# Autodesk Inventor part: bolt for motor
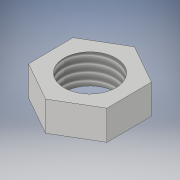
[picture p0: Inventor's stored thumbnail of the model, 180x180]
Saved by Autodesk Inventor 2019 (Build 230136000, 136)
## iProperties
Created: 2019-10
Part Number: bolt for motor
Material: Generic
Document SubType Name: Modeling
Designer: Asus
Density: 1 g/cm^3
Appearance: Default
Author: Asus
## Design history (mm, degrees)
sketch "Sketch1"
  geometry: 1 further point
sketch "Sketch2"
  geometry: L1 (10.441, 6.163)-(10.558, -5.961); L2 (10.558, -5.961)-(0.117, -12.124); L3 (0.117, -12.124)-(-10.441, -6.163); L4 (-10.441, -6.163)-(-10.558, 5.961); L5 (-10.558, 5.961)-(-0.117, 12.124); L6 (-0.117, 12.124)-(10.441, 6.163); 2 further points
  constraints: 12 end point, 1 coincident, 13 other
  dimensions: "d0" = 21 distance between parallel lines of L4 L1
extrude "Extrusion1" new body sketch "Sketch2" distance "d1" = 8; taper "d2" = 0 deg
sketch "Sketch3"
  geometry: C1 r 7 at (0, 0); 1 further point
  constraints: 1 centre point, 1 coincident
  dimensions: "d3" = 14 diameter of C1
extrude "Extrusion2" cut sketch "Sketch3" distance "d4" = 18; taper "d5" = 0 deg
thread "Thread1" dims "d6" = 10, "d7" = 0
body "Solid1"
